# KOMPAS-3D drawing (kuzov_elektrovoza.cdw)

Referenced files in C:\Documents and Settings\GooDMaN.HOME-ACDA87A129\Мои документы\Ч\: Фрагмент.frw, Фрагмент 2.frw
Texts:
  Вставь свой шифр
  Кузов электровоза
  goodman
  home PC
  Текст на чертеже
  Размерные надписи
  Шероховатость
  Линия-выноска #1
  Линия-выноска #2
  Линия-выноска #3
  Отклонения формы и база
  Заголовок таблицы
  Ячейка таблицы
  Стрелка вида
  Обозначение изменения
  Фигурная скобка
  Номер узла
  Марка координационной оси
  VRCB
  Выносная надпись
  Обозначение узла
  Марка/позиционное обозначение с линией-выноской
  Марка/позиционное обозначение на линии
  Марка/позиционное обозначение без линии-выноски
  Слой 1
  Иванов
  ПЭР.30.4.00.00.23.ВО-
Dimensions and other numbers on the sheet: 7; 1; 2; 3; 4; 5; 6; 8; 9; 10; 15200; 16420; 0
